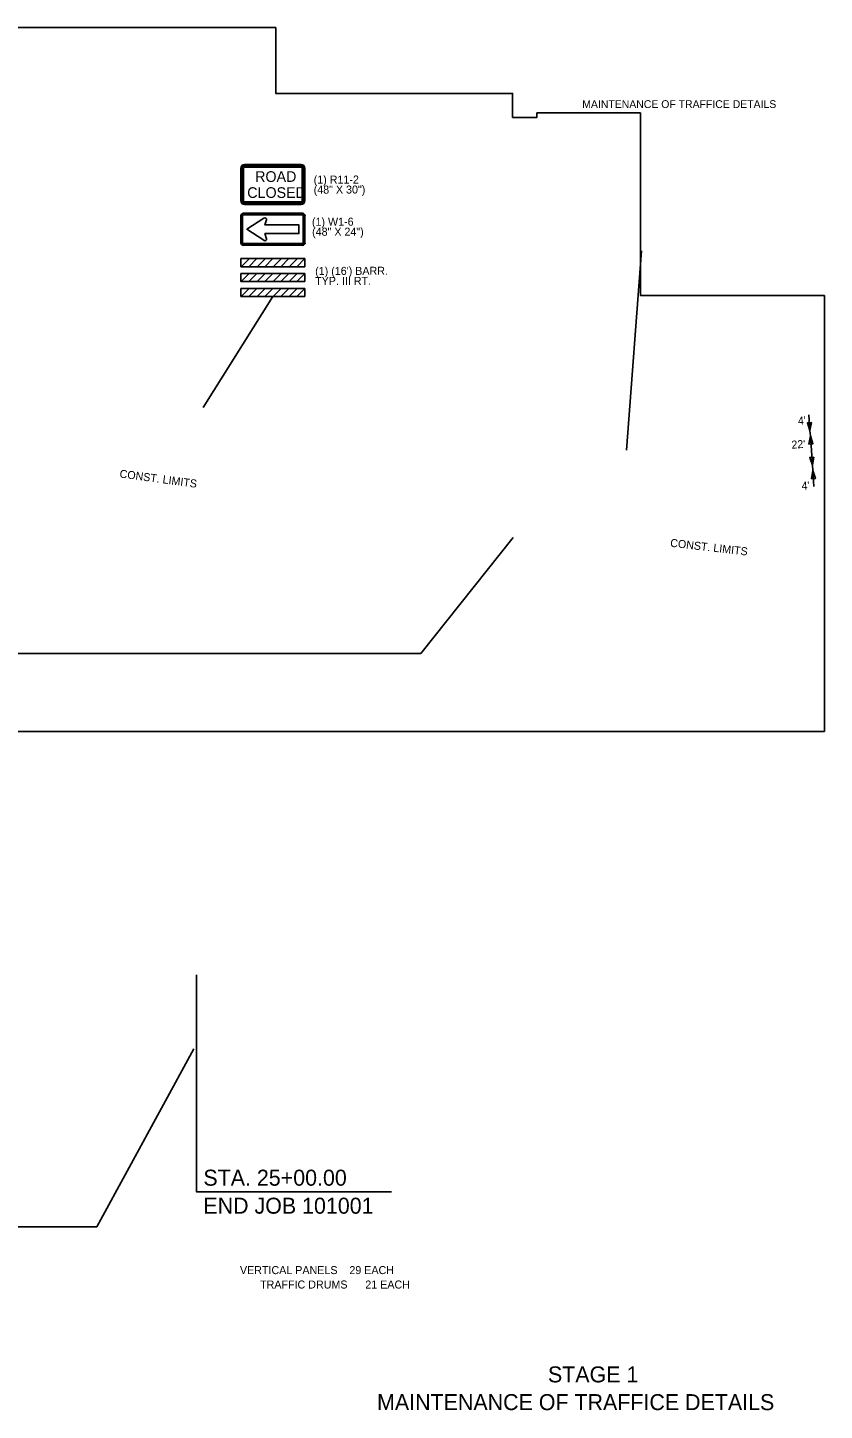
# Model space of a CAD drawing. Extents: x 1939303 to 1940899, y 534003 to 535040.
# Drawn here: x 1940301 to 1940899, y 534003 to 535040 of the extents above; entities that cross this region are included whole.
import ezdxf

# ---------------------------------------------------------------- set-up
doc = ezdxf.new("R2010")
doc.units = 0
for name, color, linetype in [('Level 3', 7, 'Continuous'), ('Level 4', 7, 'Continuous'), ('Level 8', 7, 'Continuous'), ('R_Annotation', 7, 'Continuous'), ('R_Border', 7, 'Continuous'), ('S_BASELINE', 7, 'Continuous')]:
    doc.layers.add(name, color=color, linetype=linetype)

msp = doc.modelspace()

# ---------------------------------------------------------------- linework, layer by layer
at = {"layer": 'Level 3'}
for p, q in [((1940461.3, 534866.4), (1940509.3, 534866.4)), ((1940461.3, 534860.3), (1940461.3, 534866.4)), ((1940509.3, 534860.3), (1940509.3, 534866.4)), ((1940461.3, 534860.3), (1940509.3, 534860.3)), ((1940461.3, 534855.2), (1940509.3, 534855.2)), ((1940461.3, 534849.2), (1940461.3, 534855.2)), ((1940509.3, 534860.3), (1940509.3, 534860.4)), ((1940509.3, 534849.2), (1940509.3, 534855.2)), ((1940509.3, 534849.2), (1940509.3, 534855.2)), ((1940461.3, 534849.2), (1940509.3, 534849.2)), ((1940461.3, 534844), (1940509.3, 534844)), ((1940461.3, 534838), (1940461.3, 534844)), ((1940509.3, 534838), (1940509.3, 534844)), ((1940461.3, 534838), (1940509.3, 534838))]:
    msp.add_line(p, q, dxfattribs=at)
for points in [[(1940473.3, 534866.4), (1940467.4, 534866.3), (1940461.4, 534860.3), (1940467.3, 534860.3)], [(1940485.3, 534866.4), (1940479.4, 534866.3), (1940473.4, 534860.3), (1940479.3, 534860.3)], [(1940497.3, 534866.4), (1940491.4, 534866.3), (1940485.4, 534860.3), (1940491.3, 534860.3)], [(1940509.3, 534866.4), (1940503.4, 534866.3), (1940497.4, 534860.3), (1940503.3, 534860.3)], [(1940473.3, 534855.2), (1940467.4, 534855.2), (1940461.4, 534849.2), (1940467.3, 534849.2)], [(1940485.3, 534855.2), (1940479.4, 534855.2), (1940473.4, 534849.2), (1940479.3, 534849.2)], [(1940497.3, 534855.2), (1940491.4, 534855.2), (1940485.4, 534849.2), (1940491.3, 534849.2)], [(1940509.3, 534855.2), (1940503.4, 534855.2), (1940497.4, 534849.2), (1940503.3, 534849.2)], [(1940473.3, 534844), (1940467.4, 534844), (1940461.4, 534838), (1940467.3, 534838)], [(1940485.3, 534844), (1940479.4, 534844), (1940473.4, 534838), (1940479.3, 534838)], [(1940497.3, 534844), (1940491.4, 534844), (1940485.4, 534838), (1940491.3, 534838)], [(1940509.3, 534844), (1940503.4, 534844), (1940497.4, 534838), (1940503.3, 534838)]]:
    msp.add_lwpolyline(points, close=True, dxfattribs=at)
at = {"layer": 'Level 4'}
for p, q in [((1940461.3, 534934.1), (1940461.3, 534909.7)), ((1940462.1, 534934.1), (1940462.1, 534909.7)), ((1940463.3, 534934.1), (1940463.3, 534909.7)), ((1940506.5, 534936.9), (1940464.1, 534936.9)), ((1940506.5, 534936.1), (1940464.1, 534936.1)), ((1940506.5, 534934.9), (1940464.1, 534934.9)), ((1940507.3, 534909.7), (1940507.3, 534934.1)), ((1940508.5, 534909.7), (1940508.5, 534934.1)), ((1940509.3, 534909.7), (1940509.3, 534934.1)), ((1940464.1, 534908.9), (1940506.5, 534908.9)), ((1940464.1, 534907.7), (1940506.5, 534907.7)), ((1940464.1, 534906.9), (1940506.5, 534906.9)), ((1940461.3, 534898.5), (1940461.3, 534878.2)), ((1940461.8, 534898.5), (1940461.8, 534878.2)), ((1940462.6, 534898.5), (1940462.6, 534878.2)), ((1940507.5, 534900.4), (1940463.2, 534900.4)), ((1940507.5, 534899.9), (1940463.2, 534899.9)), ((1940507.5, 534899.1), (1940463.2, 534899.1)), ((1940508.1, 534878.2), (1940508.1, 534898.5)), ((1940508.8, 534878.2), (1940508.8, 534898.5)), ((1940509.3, 534878.2), (1940509.3, 534898.5)), ((1940463.2, 534877.6), (1940507.5, 534877.6)), ((1940463.2, 534876.9), (1940507.5, 534876.9)), ((1940463.2, 534876.4), (1940507.5, 534876.4))]:
    msp.add_line(p, q, dxfattribs=at)
for points in [[(1940478.5, 534896.7), (1940465.8, 534888.4), (1940478.5, 534880.1)], [(1940480.5, 534881.3), (1940479.3, 534885.1), (1940504.8, 534885.1), (1940504.8, 534891.6), (1940479.3, 534891.6), (1940480.5, 534895.4)]]:
    msp.add_lwpolyline(points, dxfattribs=at)
for centre, radius, start, end in [((1940464.1, 534934.1), 2.8, 90, 180), ((1940464.1, 534934.1), 2, 90, 180), ((1940464.1, 534934.1), 0.8, 90, 180), ((1940506.5, 534934.1), 2.8, 360, 90), ((1940506.5, 534934.1), 2, 360, 90), ((1940506.5, 534934.1), 0.8, 360, 90), ((1940464.1, 534909.7), 2.8, 180, 270), ((1940464.1, 534909.7), 2, 180, 270), ((1940464.1, 534909.7), 0.8, 180, 270), ((1940506.5, 534909.7), 2.8, 270, 360), ((1940506.5, 534909.7), 2, 270, 360), ((1940506.5, 534909.7), 0.8, 270, 360), ((1940463.2, 534898.5), 1.88, 90, 180), ((1940463.2, 534898.5), 1.38, 90, 180), ((1940463.2, 534898.5), 0.625, 90, 180), ((1940451.1, 534938.5), 50, 303.2286, 303.4755), ((1940479.3, 534895.8), 1.2, 344.0309, 123.4755), ((1940507.5, 534898.5), 1.88, 360, 90), ((1940507.5, 534898.5), 1.38, 360, 90), ((1940507.5, 534898.5), 0.625, 360, 90), ((1940463.2, 534878.2), 1.88, 180, 270), ((1940463.2, 534878.2), 1.38, 180, 270), ((1940463.2, 534878.2), 0.625, 180, 270), ((1940451.2, 534838.2), 50, 56.5994, 56.857), ((1940479.3, 534880.9), 1.18, 236.5994, 15.9691), ((1940507.5, 534878.2), 1.88, 270, 360), ((1940507.5, 534878.2), 1.37, 270, 360), ((1940507.5, 534878.2), 0.625, 270, 360)]:
    msp.add_arc(centre, radius, start, end, dxfattribs=at)
at = {"layer": 'Level 8'}
msp.add_lwpolyline([(1940750.3, 534722.8), (1940761.7, 534872.3)], dxfattribs=at)
at = {"layer": 'R_Annotation'}
msp.add_line((1939303.3, 534511.9), (1940898.7, 534511.9), dxfattribs=at)
at = {"layer": 'R_Border'}
for points in [[(1940898.7, 534838.7), (1940898.7, 534511.9), (1939303.3, 534511.9), (1939303.3, 535039.6), (1940487.4, 535039.6), (1940487.4, 534990.2), (1940665, 534990.2), (1940665, 534972.3), (1940683.2, 534972.3), (1940683.2, 534975.6), (1940760.9, 534975.6)], [(1940760.9, 534975.6), (1940760.9, 534838.7), (1940898.7, 534838.7)]]:
    msp.add_lwpolyline(points, dxfattribs=at)
at = {"layer": 'S_BASELINE'}
for p, q in [((1940433.1, 534754.8), (1940485.3, 534838)), ((1940887.1, 534749.3), (1940887.9, 534737.4)), ((1940887.9, 534737.4), (1940888.2, 534733.4)), ((1940888.2, 534733.4), (1940889.8, 534711.4)), ((1940889.8, 534711.4), (1940890, 534707.4)), ((1940890, 534707.4), (1940890.9, 534695.5))]:
    msp.add_line(p, q, dxfattribs=at)
for points in [[(1940889, 534743.4), (1940887.9, 534737.4), (1940886, 534743.2)], [(1940887.1, 534727.3), (1940888.2, 534733.4), (1940890.1, 534727.5)], [(1940890.8, 534717.5), (1940889.8, 534711.4), (1940887.8, 534717.3)], [(1940889, 534701.3), (1940890, 534707.4), (1940892, 534701.5)]]:
    msp.add_lwpolyline(points, close=True, dxfattribs=at)
for points in [[(1939644, 534715), (1939920, 534570.3), (1940596.1, 534570.3), (1940665.5, 534657.3)], [(1940428, 534329.3), (1940428, 534166.7), (1940574.2, 534166.7)], [(1939822.9, 534202.3), (1939878.2, 534140.3), (1940353.3, 534140.3), (1940426, 534273.8)]]:
    msp.add_lwpolyline(points, dxfattribs=at)

# ---------------------------------------------------------------- texts
at = {"layer": 'Level 4'}
for s, p in [('ROAD', (1940472, 534923.9)), ('CLOSED', (1940466.1, 534911.9))]:
    msp.add_text(s, height=8, rotation=360, dxfattribs=at).set_placement(p)
at = {"layer": 'R_Annotation'}
msp.add_text('MAINTENANCE OF TRAFFICE DETAILS', height=5.862, dxfattribs=at).set_placement((1940717.2, 534979.3))
at = {"layer": 'S_BASELINE'}
for s, rotation, p in [('(1) R11-2', 0.1719, (1940515.9, 534922.6)), ('(48" X 30")', 0.1719, (1940515.9, 534915.1)), ('(1) W1-6 ', 0.1558, (1940514.6, 534891)), ('(48" X 24")', 0.1558, (1940514.7, 534883.5)), ("(1) (16') BARR.", 0.1719, (1940517, 534854.1)), ('TYP. III RT.', 0.1719, (1940517, 534846.6)), ("4'", 3.9991, (1940879.1, 534741.7)), ("22'", 3.9991, (1940874.2, 534723.8)), ('CONST. LIMITS', 352.3283, (1940370.1, 534702.3)), ("4'", 3.9991, (1940881.8, 534692.9)), ('CONST. LIMITS', 353.4008, (1940782.9, 534650.4))]:
    msp.add_text(s, height=6, rotation=rotation, dxfattribs=at).set_placement(p)
for s, height, p in [('STA. 25+00.00', 12, (1940433.2, 534171.2)), ('END JOB 101001', 12, (1940433.2, 534150.2)), ('    VERTICAL PANELS    29 EACH', 6, (1940451.7, 534104.9)), ('TRAFFIC DRUMS      21 EACH', 6, (1940475.7, 534094.1)), ('STAGE 1', 12, (1940691.5, 534023.7)), ('MAINTENANCE OF TRAFFICE DETAILS', 12, (1940563.4, 534002.9))]:
    msp.add_text(s, height=height, dxfattribs=at).set_placement(p)

doc.saveas('drawing.dxf')
